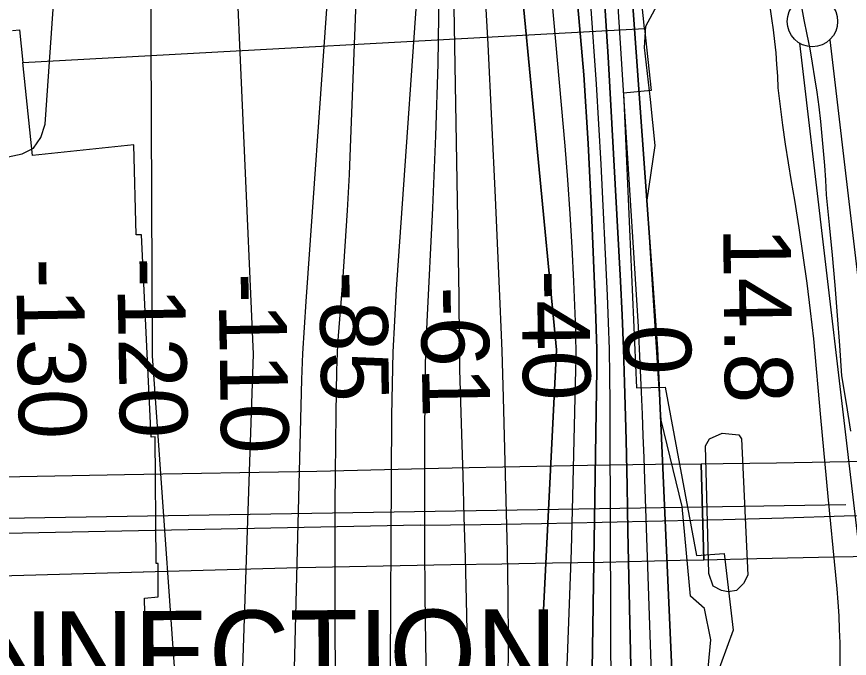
# Model space of a CAD drawing. Extents: x 3677843 to 3715951, y 511991 to 537744.
# Drawn here: x 3685277 to 3686102, y 525377 to 526013 of the extents above; entities that cross this region are included whole.
import ezdxf

# ---------------------------------------------------------------- set-up
doc = ezdxf.new("R2010")
doc.units = 0
for name, color, linetype in [('V-BRDG-IDEN', 7, 'Continuous'), ('V-BRDG-OTLN', 7, 'Continuous'), ('V-CHAN-DOCK', 7, 'Continuous'), ('V-FLOD-BASE', 7, 'Continuous'), ('V-LEVE-TOET', 7, 'Continuous'), ('V-RIVR-EDGE', 7, 'Continuous'), ('V-RIVR-RANG', 7, 'Continuous'), ('V-ROAD-CNTR', 7, 'Continuous'), ('V-RRAP-RVMT', 7, 'Continuous'), ('V-SURV-LINE', 7, 'Continuous'), ('V-TOPO-DPTH', 7, 'Continuous'), ('V-TOPO-MAJR', 7, 'Continuous'), ('V-TOPO-MINR', 7, 'Continuous'), ('V-TOPO-WATR', 7, 'Continuous')]:
    doc.layers.add(name, color=color, linetype=linetype)

msp = doc.modelspace()

# ---------------------------------------------------------------- linework, layer by layer
at = {"layer": 'V-BRDG-OTLN'}
msp.add_lwpolyline([(3685954.94, 525569.95), (3685976.6, 525570.17), (3686029.39, 525571.03), (3686082.19, 525571.97), (3686134.98, 525572.99), (3686187.77, 525574.1), (3686240.55, 525575.27), (3686293.32, 525576.53), (3686346.09, 525577.87), (3686400.68, 525578.96), (3686455.28, 525580.06), (3686486.3, 525580.68), (3686489.88, 525485.06), (3686468.62, 525484.55), (3686391.26, 525482.5), (3686315.04, 525481.38), (3686238.82, 525480.15), (3686162.59, 525478.81), (3686086.37, 525477.37), (3686010.14, 525475.81), (3685957.59, 525474.67)], close=True, dxfattribs=at)
for points in [[(3685193.12, 525555.74), (3685383.64, 525559.25), (3685574.17, 525562.59), (3685641.23, 525564.43), (3685708.3, 525566.04), (3685775.37, 525567.41), (3685842.44, 525568.56), (3685909.52, 525569.48), (3685954.94, 525569.95), (3685957.59, 525474.67), (3685933.92, 525474.15), (3685857.69, 525472.38), (3685807.49, 525471.57), (3685757.29, 525470.72), (3685707.09, 525469.82), (3685656.88, 525468.87), (3685606.68, 525467.88), (3685556.47, 525466.84), (3685248.19, 525458.46)], [(3685676.67, 525509.03), (3685736.67, 525509.92), (3685796.67, 525510.96), (3685856.66, 525512.15), (3685916.65, 525513.48), (3685976.63, 525514.96), (3686036.61, 525516.59), (3686096.58, 525518.37), (3686176.27, 525519.24), (3686255.96, 525520.17), (3686335.65, 525521.17), (3686415.33, 525522.22), (3686488.45, 525523.19)], [(3685676.67, 525509.03), (3684707.53, 525489.88), (3683947.86, 525463.51), (3683833.54, 525464.45), (3683576.04, 525466.57)]]:
    msp.add_lwpolyline(points, dxfattribs=at)
at = {"layer": 'V-CHAN-DOCK'}
msp.add_lwpolyline([(3685962.58, 525461.2), (3685959.03, 525587.83), (3685963.19, 525594.69), (3685975.6, 525600.14), (3685992.11, 525598.69), (3685994.84, 525594.55), (3686001.11, 525459.65), (3685996.95, 525451.41), (3685990.03, 525444.56), (3685981.77, 525443.22), (3685974.89, 525444.62), (3685966.66, 525448.79)], close=True, dxfattribs=at)
at = {"layer": 'V-FLOD-BASE'}
msp.add_lwpolyline([(3686047.93, 526056.8), (3686056.7, 526009.46), (3686059.62, 525995.2), (3686062.35, 525980.9), (3686064.88, 525966.57), (3686067.2, 525952.2), (3686069.33, 525937.8), (3686071.26, 525923.37), (3686072.98, 525908.92), (3686074.51, 525894.45), (3686075.84, 525879.95), (3686076.96, 525865.44), (3686077.89, 525850.92), (3686078.61, 525836.38), (3686081.64, 525806.53), (3686084.48, 525776.66), (3686087.11, 525746.77), (3686089.54, 525716.86), (3686091.76, 525686.94), (3686093.78, 525657.01), (3686098.4, 525629.68), (3686102.75, 525602.32)], dxfattribs=at)
at = {"layer": 'V-LEVE-TOET'}
msp.add_lwpolyline([(3686022.84, 526022.39), (3686024.63, 526011.04), (3686026.21, 525999.65), (3686027.56, 525988.24), (3686028.7, 525976.81), (3686029.61, 525965.35), (3686030.31, 525953.88), (3686030.79, 525942.4), (3686033.05, 525923.76), (3686035.51, 525905.14), (3686038.18, 525886.55), (3686041.04, 525867.98), (3686044.11, 525849.45), (3686047.39, 525830.96), (3686051.64, 525803.6), (3686055.66, 525776.21), (3686059.43, 525748.78), (3686062.97, 525721.32), (3686066.26, 525693.83), (3686073.21, 525615.71), (3686080.44, 525537.61), (3686087.96, 525459.54), (3686089.2, 525446.18), (3686090.23, 525432.8), (3686091.06, 525419.41), (3686091.69, 525406.01), (3686092.11, 525392.6), (3686092.33, 525379.19), (3686092.35, 525365.77)], dxfattribs=at)
at = {"layer": 'V-RIVR-EDGE'}
msp.add_lwpolyline([(3685960.89, 525357.17), (3685964.58, 525395.58), (3685958.06, 525426.81), (3685944.28, 525438.85), (3685936.09, 525527.72), (3685915.29, 525613.02), (3685906.05, 525757.72), (3685901.42, 525830.97), (3685909.36, 525884.98), (3685904.67, 525930.62), (3685898.8, 525982.26), (3685900.05, 526003.27), (3685913.32, 526027.85)], dxfattribs=at)
at = {"layer": 'V-ROAD-CNTR'}
msp.add_lwpolyline([(3682737.44, 525473.15), (3683036.3, 525481.11), (3683311.61, 525484.49), (3686098.29, 525529.54)], dxfattribs=at)
at = {"layer": 'V-RRAP-RVMT'}
for points in [[(3685272.78, 525998.92), (3685279.58, 525999.62), (3685282.99, 525967.24), (3685898.86, 526001.05), (3685894.42, 526043.4), (3685901.22, 526078.02), (3685891.63, 526189.9), (3685904.74, 526192.43), (3685895.44, 526217.54), (3685882.7, 526217.37), (3685825.31, 526354.24), (3685824.9, 526359.43), (3685823.12, 526359.47), (3685819.01, 526369.27), (3685823.78, 526369.72), (3685821.43, 526390.09), (3685825.7, 526390.42), (3685815.2, 526539.32), (3685746.64, 526535.1), (3685746.52, 526535.76), (3685749.72, 526535.94), (3685738.25, 526823.56)], [(3685410.1, 525596.42), (3685400.48, 525796.55), (3685395.3, 525796.57), (3685392.83, 525885.88), (3685292.67, 525875.36), (3685282.99, 525967.24), (3685898.86, 526001.05)], [(3685898.86, 526001.05), (3685905.29, 525939.7), (3685878.02, 525936.83), (3685890.91, 525645.29), (3685919.27, 525645.95)], [(3685919.27, 525645.95), (3685950.2, 525479.18), (3685977.5, 525481.14), (3685986.61, 525405.1), (3685955.28, 525319.43), (3685926.6, 525326.59), (3685927.25, 525239.05), (3685925.33, 525239.14), (3685919.23, 525061.42), (3685934.89, 525061)], [(3685404.76, 525038.75), (3685403.49, 525258.3), (3685407.58, 525258.25), (3685403.66, 525436.88), (3685417.14, 525438.18), (3685417.02, 525471.08), (3685415.22, 525471.13), (3685413.99, 525596.59), (3685410.1, 525596.42)]]:
    msp.add_lwpolyline(points, dxfattribs=at)
at = {"layer": 'V-SURV-LINE'}
for points in [[(3686082.29, 525989.86), (3686150.7, 525408.45)], [(3686120.91, 525404.93), (3686052.5, 525986.34)]]:
    msp.add_lwpolyline(points, dxfattribs=at)
msp.add_circle((3686065.06, 526007.95), 25, dxfattribs=at)
at = {"layer": 'V-TOPO-DPTH'}
for points in [[(3685642.5, 527517.39), (3685849.49, 526392.84), (3685853.92, 526367.51), (3685858.06, 526342.14), (3685861.75, 526316.69), (3685865.15, 526291.2), (3685868.13, 526265.66), (3685870.84, 526240.09), (3685873.15, 526214.48), (3685875.2, 526188.85), (3685911.51, 525684.2), (3685932.06, 525225.25)], [(3685705.03, 527041.11), (3685819.08, 526384.4), (3685822.67, 526362.7), (3685826.04, 526340.97), (3685829.06, 526319.19), (3685831.85, 526297.38), (3685841.3, 526218.55), (3685848.05, 526157.24), (3685854.01, 526095.86), (3685858.77, 526034.38), (3685862.74, 525972.83), (3685874.89, 525750.67), (3685876.56, 525717.19), (3685878, 525683.7), (3685879.1, 525650.2), (3685879.97, 525616.7), (3685880.46, 525593.43), (3685881.42, 525548.29), (3685882.39, 525503.14), (3685883.38, 525457.99), (3685884.37, 525412.85), (3685887.6, 525268.01)], [(3685887.6, 525268.01), (3685884.37, 525412.85), (3685883.38, 525457.99), (3685882.39, 525503.14), (3685881.42, 525548.29), (3685880.46, 525593.43), (3685879.97, 525616.7), (3685879.1, 525650.2), (3685878, 525683.7), (3685876.56, 525717.19), (3685874.89, 525750.67), (3685862.74, 525972.83), (3685858.77, 526034.38), (3685854.01, 526095.86), (3685848.05, 526157.24), (3685841.3, 526218.55), (3685831.85, 526297.38), (3685829.06, 526319.19), (3685826.04, 526340.97), (3685822.67, 526362.7), (3685819.08, 526384.4), (3685705.03, 527041.11)], [(3685673.83, 526815.26), (3685693.15, 526695.68), (3685736.74, 526408.42), (3685741.81, 526373.24), (3685746.56, 526338.02), (3685750.79, 526302.73), (3685754.69, 526267.4), (3685755.97, 526254.97), (3685760.21, 526213.38), (3685764.39, 526171.79), (3685768.49, 526130.19), (3685772.53, 526088.59), (3685811.52, 525682.76), (3685790.7, 525266.46)], [(3685673.83, 526815.26), (3685693.15, 526695.68), (3685736.74, 526408.42), (3685741.81, 526373.24), (3685746.56, 526338.02), (3685750.79, 526302.73), (3685754.69, 526267.4), (3685755.97, 526254.97), (3685760.21, 526213.38), (3685764.39, 526171.79), (3685768.49, 526130.19), (3685772.53, 526088.59), (3685811.52, 525682.76), (3685790.7, 525266.46)], [(3685846.02, 525302.35), (3685851.34, 525642.89), (3685851.49, 525663.11), (3685851.4, 525683.34), (3685850.98, 525703.55), (3685850.32, 525723.77), (3685846.41, 525819.29), (3685842.93, 525887.22), (3685838.53, 525955.07), (3685832.73, 526022.82), (3685826.01, 526090.5), (3685800.38, 526324.12), (3685799.45, 526332.06), (3685798.45, 526340), (3685797.33, 526347.91), (3685796.14, 526355.82), (3685765.72, 526548.23), (3685748.9, 526652.27), (3685731.6, 526756.23)], [(3685731.6, 526756.23), (3685748.9, 526652.27), (3685765.72, 526548.23), (3685796.14, 526355.82), (3685797.33, 526347.91), (3685798.45, 526340), (3685799.45, 526332.06), (3685800.38, 526324.12), (3685826.01, 526090.5), (3685832.73, 526022.82), (3685838.53, 525955.07), (3685842.93, 525887.22), (3685846.41, 525819.29), (3685850.32, 525723.77), (3685850.98, 525703.55), (3685851.4, 525683.34), (3685851.49, 525663.11), (3685851.34, 525642.89), (3685846.02, 525302.35)], [(3685820.15, 525324.93), (3685822.47, 525378.07), (3685824.56, 525431.22), (3685826.29, 525484.38), (3685827.78, 525537.55), (3685830.88, 525663.2), (3685831.03, 525673.12), (3685831.06, 525683.04), (3685830.89, 525692.97), (3685830.59, 525702.89), (3685828.71, 525750.36), (3685827.12, 525784.01), (3685825.21, 525817.63), (3685822.79, 525851.22), (3685820.04, 525884.79), (3685788.34, 526239.31)], [(3685820.15, 525324.93), (3685822.47, 525378.07), (3685824.56, 525431.22), (3685826.29, 525484.38), (3685827.78, 525537.55), (3685830.88, 525663.2), (3685831.03, 525673.12), (3685831.06, 525683.04), (3685830.89, 525692.97), (3685830.59, 525702.89), (3685828.71, 525750.36), (3685827.12, 525784.01), (3685825.21, 525817.63), (3685822.79, 525851.22), (3685820.04, 525884.79), (3685788.34, 526239.31)]]:
    msp.add_lwpolyline(points, dxfattribs=at)
at = {"layer": 'V-TOPO-MAJR'}
for points in [[(3685763.57, 525350.44), (3685764, 525394.71), (3685763.71, 525438.99), (3685762.94, 525483.26), (3685759.05, 525635.66), (3685758.39, 525658.82), (3685757.65, 525681.98), (3685756.77, 525705.13), (3685755.81, 525728.28), (3685751.13, 525833.71), (3685747.58, 525909.55), (3685743.79, 525985.39), (3685739.63, 526061.21), (3685735.23, 526137.01), (3685725.95, 526290.51), (3685724.29, 526313.85), (3685722.3, 526337.15), (3685719.82, 526360.41), (3685717.02, 526383.63), (3685684.92, 526627.6), (3685671.7, 526718.74), (3685656.88, 526809.59)], [(3685551.47, 525341.54), (3685558.57, 525627.46), (3685559.39, 525653.29), (3685560.46, 525679.11), (3685561.87, 525704.91), (3685563.53, 525730.69), (3685584.51, 526025.13)]]:
    msp.add_lwpolyline(points, dxfattribs=at)
at = {"layer": 'V-TOPO-MINR'}
for points in [[(3685440.9, 525261.62), (3685411.56, 525677), (3685408.74, 526299.89), (3685408.49, 526312.73), (3685407.96, 526325.56), (3685407.05, 526338.37), (3685405.87, 526351.16), (3685388.87, 526508.58), (3685378.34, 526599.99), (3685366.95, 526691.28), (3685354.26, 526782.41), (3685340.71, 526873.41), (3685237.36, 527534.85), (3685140.08, 527990.04)], [(3685497.51, 525271.32), (3685511.55, 525678.44), (3685482.86, 526328.34), (3685402.61, 526771.83), (3685379.8, 526899.26), (3685357.32, 527026.74), (3685335.33, 527154.3), (3685313.67, 527281.93), (3685276.4, 527504.15), (3685273.59, 527520.7), (3685270.75, 527537.24), (3685267.86, 527553.78), (3685264.93, 527570.3), (3685243.51, 527689.88), (3685229.62, 527766.14), (3685215.41, 527842.35), (3685200.75, 527918.47)], [(3685909.55, 525246.64), (3685899.06, 525554.57), (3685898.3, 525576.13), (3685897.52, 525597.7), (3685896.69, 525619.26), (3685895.84, 525640.83), (3685894.9, 525662.38), (3685893.85, 525683.94), (3685892.67, 525705.48), (3685891.39, 525727.02), (3685869.2, 526080.2), (3685866.07, 526123.9), (3685862.41, 526167.55), (3685857.98, 526211.13), (3685853.03, 526254.65), (3685849.64, 526282.34), (3685845.75, 526311.95), (3685841.54, 526341.52), (3685836.84, 526371.01), (3685831.81, 526400.45), (3685673.54, 527283.01)], [(3685887.6, 525268.01), (3685884.37, 525412.85), (3685883.38, 525457.99), (3685882.39, 525503.14), (3685881.42, 525548.29), (3685880.46, 525593.43), (3685879.97, 525616.7), (3685879.1, 525650.2), (3685878, 525683.7), (3685876.56, 525717.19), (3685874.89, 525750.67), (3685862.74, 525972.83), (3685858.77, 526034.38), (3685854.01, 526095.86), (3685848.05, 526157.24), (3685841.3, 526218.55), (3685831.85, 526297.38), (3685829.06, 526319.19), (3685826.04, 526340.97), (3685822.67, 526362.7), (3685819.08, 526384.4), (3685705.03, 527041.11)], [(3685268.39, 525874.07), (3685282.28, 525876.83), (3685293.49, 525882.62), (3685300.71, 525892.98), (3685305.27, 525906.38), (3685330.51, 526271.89), (3685331.58, 526297.35), (3685331.74, 526322.79), (3685330.53, 526348.2), (3685328.41, 526373.6), (3685285.16, 526763.68), (3685269.87, 526891.93)], [(3685790.7, 525266.46), (3685811.52, 525682.76), (3685772.53, 526088.59), (3685768.49, 526130.19), (3685764.39, 526171.79), (3685760.21, 526213.38), (3685755.97, 526254.97), (3685754.69, 526267.4), (3685750.79, 526302.73), (3685746.56, 526338.02), (3685741.81, 526373.24), (3685736.74, 526408.42), (3685693.15, 526695.68), (3685673.83, 526815.26)], [(3685865.77, 525352.84), (3685865.47, 525397.24), (3685865.25, 525441.65), (3685865.1, 525486.05), (3685864.73, 525630.44), (3685864.48, 525656.98), (3685864, 525683.51), (3685863.16, 525710.03), (3685862.08, 525736.55), (3685855.9, 525866.72), (3685851.33, 525945.91), (3685845.69, 526025.01), (3685838.44, 526103.99), (3685830.12, 526182.87), (3685815.22, 526311.48), (3685813.43, 526325.98), (3685811.49, 526340.46), (3685809.34, 526354.91), (3685807.05, 526369.34), (3685737.14, 526788.56)], [(3685726.24, 525267.71), (3685722.32, 525435.39), (3685721.32, 525476.39), (3685720.26, 525517.39), (3685719.1, 525558.39), (3685717.89, 525599.38), (3685715.93, 525663.34), (3685715.7, 525672.36), (3685715.53, 525681.38), (3685715.44, 525690.4), (3685715.41, 525699.41), (3685715.4, 525708.43), (3685715.35, 525717.45), (3685715.25, 525726.47), (3685715.12, 525735.49), (3685705.23, 526308.14), (3685704.78, 526322.33), (3685704.06, 526336.5), (3685702.93, 526350.65), (3685701.52, 526364.78), (3685679.74, 526555.7), (3685671.28, 526620.35), (3685661.42, 526684.76), (3685649.44, 526748.81)], [(3685846.02, 525302.35), (3685851.34, 525642.89), (3685851.49, 525663.11), (3685851.4, 525683.34), (3685850.98, 525703.55), (3685850.32, 525723.77), (3685846.41, 525819.29), (3685842.93, 525887.22), (3685838.53, 525955.07), (3685832.73, 526022.82), (3685826.01, 526090.5), (3685800.38, 526324.12), (3685799.45, 526332.06), (3685798.45, 526340), (3685797.33, 526347.91), (3685796.14, 526355.82), (3685765.72, 526548.23), (3685748.9, 526652.27), (3685731.6, 526756.23)], [(3685592.61, 525270.41), (3685592.39, 525500.47), (3685592.44, 525530.34), (3685592.6, 525560.2), (3685592.91, 525590.06), (3685593.32, 525619.92), (3685594.03, 525662.4), (3685594.25, 525671.01), (3685594.58, 525679.62), (3685595.06, 525688.22), (3685595.65, 525696.81), (3685599.82, 525750.25), (3685602.36, 525785.57), (3685604.62, 525820.91), (3685606.47, 525856.27), (3685608.03, 525891.65), (3685623.32, 526291.46)], [(3685820.15, 525324.93), (3685822.47, 525378.07), (3685824.56, 525431.22), (3685826.29, 525484.38), (3685827.78, 525537.55), (3685830.88, 525663.2), (3685831.03, 525673.12), (3685831.06, 525683.04), (3685830.89, 525692.97), (3685830.59, 525702.89), (3685828.71, 525750.36), (3685827.12, 525784.01), (3685825.21, 525817.63), (3685822.79, 525851.22), (3685820.04, 525884.79), (3685788.34, 526239.31)], [(3685646.87, 525308.84), (3685648.57, 525617.8), (3685649.04, 525649.1), (3685649.92, 525680.38), (3685651.39, 525711.64), (3685653.26, 525742.89), (3685679.15, 526114.73)], [(3685684.49, 525264.87), (3685682.24, 525392.09), (3685681.56, 525440.22), (3685681.13, 525488.35), (3685681.05, 525536.49), (3685681.2, 525584.62), (3685681.66, 525651.23), (3685681.86, 525666.06), (3685682.19, 525680.88), (3685682.71, 525695.7), (3685683.36, 525710.52), (3685689.05, 525823.37), (3685692.04, 525894.62), (3685694.24, 525965.89), (3685695.25, 526037.19)]]:
    msp.add_lwpolyline(points, dxfattribs=at)
at = {"layer": 'V-TOPO-WATR'}
msp.add_lwpolyline([(3685932.06, 525225.25), (3685911.51, 525684.2), (3685875.2, 526188.85), (3685873.15, 526214.48), (3685870.84, 526240.09), (3685868.13, 526265.66), (3685865.15, 526291.2), (3685861.75, 526316.69), (3685858.06, 526342.14), (3685853.92, 526367.51), (3685849.49, 526392.84), (3685642.5, 527517.39)], dxfattribs=at)

# ---------------------------------------------------------------- texts
at = {"layer": 'V-BRDG-IDEN'}
msp.add_text('CONNECTION', height=83, rotation=0.25227, dxfattribs=at).set_placement((3685066.43, 525339.74))
at = {"layer": 'V-RIVR-RANG'}
for s, rotation, p in [('14.8', 270.68833, (3685976.58, 525803.93)), ('14.8', 270.68833, (3685976.58, 525803.93)), ('-130', 270.96739, (3685276.42, 525773.1)), ('-120', 270.96739, (3685376.42, 525774.01)), ('-110', 270.96739, (3685476.7, 525758.58)), ('-85', 270.96739, (3685576.68, 525760.28)), ('-40', 270.68833, (3685777.07, 525761.49)), ('-61', 270.96739, (3685676.95, 525745.11)), ('0', 270.68833, (3685877.73, 525707.54)), ('0', 270.68833, (3685877.73, 525707.54))]:
    msp.add_text(s, height=67, rotation=rotation, dxfattribs=at).set_placement(p)

doc.saveas('drawing.dxf')
